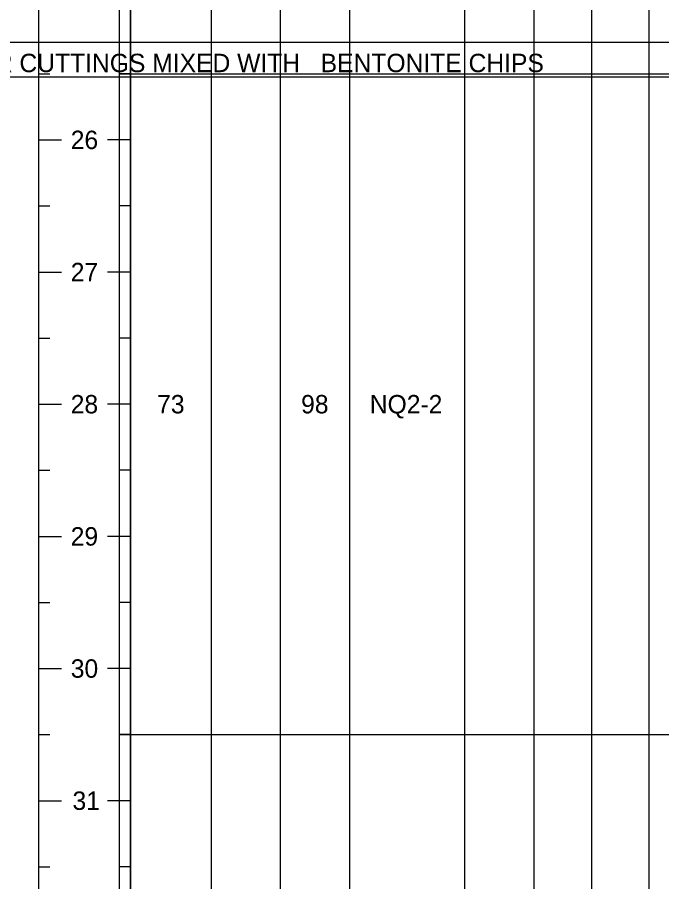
# Model space of a CAD drawing. Extents: x 0 to 0.83, y -0.65 to 1.27.
# Drawn here: x 0.3715 to 0.6046, y -0.3163 to -0.0035 of the extents above; entities that cross this region are included whole.
import ezdxf

# ---------------------------------------------------------------- set-up
doc = ezdxf.new("R2010")
doc.units = 0

msp = doc.modelspace()

# ---------------------------------------------------------------- linework, layer by layer
for points in [[(0.4125, 1.22083), (0.4125, -0.64575)], [(0.4125, 1.22083), (0.4125, -0.64575)], [(0.44167, 1.22083), (0.44167, -0.64575)], [(0.46667, 1.22083), (0.46667, -0.64575)], [(0.49167, 1.22083), (0.49167, -0.64575)], [(0.53333, 1.22083), (0.53333, -0.64575)], [(0.55833, 1.22083), (0.55833, -0.64575)], [(0.57917, 1.20833), (0.57917, -0.64575)], [(0.6, 1.20833), (0.6, -0.64575)], [(0.37917, 1.19583), (0.37917, -0.64575)], [(0, 0.0875), (0, -0.025), (0.83333, -0.025), (0.83333, 0.0875)], [(0.40833, 0.07175), (0.40833, -0.02392)], [(0, -0.0125), (0.83333, -0.0125)], [(0.37917, -0.02392), (0.38333, -0.02392)], [(0.40833, -0.02392), (0.4125, -0.02392)], [(0.40833, -0.02392), (0.40833, -0.26308)], [(0.40833, -0.02392), (0.4125, -0.02392)], [(0.4125, -0.02392), (0.40833, -0.02392)], [(0.4125, -0.02392), (0.44167, -0.02392)], [(0.44167, -0.02392), (0.46667, -0.02392)], [(0.46667, -0.02392), (0.49167, -0.02392)], [(0.49167, -0.02392), (0.53333, -0.02392)], [(0.53333, -0.02392), (0.55833, -0.02392)], [(0.55833, -0.02392), (0.57917, -0.02392)], [(0.57917, -0.02392), (0.6, -0.02392)], [(0.6, -0.02392), (0.62083, -0.02392)], [(0.37917, -0.04783), (0.3875, -0.04783)], [(0.37917, -0.04783), (0.38333, -0.04783)], [(0.4125, -0.04783), (0.40417, -0.04783)], [(0.4125, -0.04783), (0.40833, -0.04783)], [(0.37917, -0.07175), (0.38333, -0.07175)], [(0.4125, -0.07175), (0.40833, -0.07175)], [(0.37917, -0.09567), (0.3875, -0.09567)], [(0.37917, -0.09567), (0.38333, -0.09567)], [(0.4125, -0.09567), (0.40417, -0.09567)], [(0.4125, -0.09567), (0.40833, -0.09567)], [(0.37917, -0.11958), (0.38333, -0.11958)], [(0.4125, -0.11958), (0.40833, -0.11958)], [(0.37917, -0.1435), (0.3875, -0.1435)], [(0.37917, -0.1435), (0.38333, -0.1435)], [(0.4125, -0.1435), (0.40417, -0.1435)], [(0.4125, -0.1435), (0.40833, -0.1435)], [(0.37917, -0.16742), (0.38333, -0.16742)], [(0.4125, -0.16742), (0.40833, -0.16742)], [(0.37917, -0.19133), (0.3875, -0.19133)], [(0.37917, -0.19133), (0.38333, -0.19133)], [(0.4125, -0.19133), (0.40417, -0.19133)], [(0.4125, -0.19133), (0.40833, -0.19133)], [(0.37917, -0.21525), (0.38333, -0.21525)], [(0.4125, -0.21525), (0.40833, -0.21525)], [(0.37917, -0.23917), (0.3875, -0.23917)], [(0.37917, -0.23917), (0.38333, -0.23917)], [(0.4125, -0.23917), (0.40417, -0.23917)], [(0.4125, -0.23917), (0.40833, -0.23917)], [(0.37917, -0.26308), (0.38333, -0.26308)], [(0.40833, -0.26308), (0.4125, -0.26308)], [(0.40833, -0.26308), (0.40833, -0.50225)], [(0.40833, -0.26308), (0.4125, -0.26308)], [(0.4125, -0.26308), (0.40833, -0.26308)], [(0.4125, -0.26308), (0.44167, -0.26308)], [(0.44167, -0.26308), (0.46667, -0.26308)], [(0.46667, -0.26308), (0.49167, -0.26308)], [(0.49167, -0.26308), (0.53333, -0.26308)], [(0.53333, -0.26308), (0.55833, -0.26308)], [(0.55833, -0.26308), (0.57917, -0.26308)], [(0.57917, -0.26308), (0.6, -0.26308)], [(0.6, -0.26308), (0.62083, -0.26308)], [(0.37917, -0.287), (0.3875, -0.287)], [(0.37917, -0.287), (0.38333, -0.287)], [(0.4125, -0.287), (0.40417, -0.287)], [(0.4125, -0.287), (0.40833, -0.287)], [(0.37917, -0.31092), (0.38333, -0.31092)], [(0.4125, -0.31092), (0.40833, -0.31092)]]:
    msp.add_lwpolyline(points)
for points in [[(0.40833, -0.02392), (0.4125, -0.02392), (0.4125, 0.07175), (0.40833, 0.07175)], [(0.40833, -0.26308), (0.4125, -0.26308), (0.4125, -0.02392), (0.40833, -0.02392)], [(0.40833, -0.50225), (0.4125, -0.50225), (0.4125, -0.26308), (0.40833, -0.26308)]]:
    msp.add_lwpolyline(points, close=True)

# ---------------------------------------------------------------- texts
for s, height, p in [('ASPHALT PATCH; AUGER CUTTINGS MIXED WITH   BENTONITE CHIPS', 0.0066667, (0.25986, -0.02333)), ('26', 0.006667, (0.39087, -0.05117)), ('27', 0.006667, (0.39087, -0.099)), ('28', 0.006667, (0.39086, -0.14683)), ('73', 0.006667, (0.42212, -0.14683)), ('98', 0.006667, (0.47419, -0.14683)), ('NQ2-2', 0.006667, (0.49903, -0.14683)), ('29', 0.006667, (0.39086, -0.19467)), ('30', 0.006667, (0.39088, -0.2425)), ('31', 0.006667, (0.39151, -0.29033))]:
    msp.add_text(s, height=height).set_placement(p)

doc.saveas('drawing.dxf')
